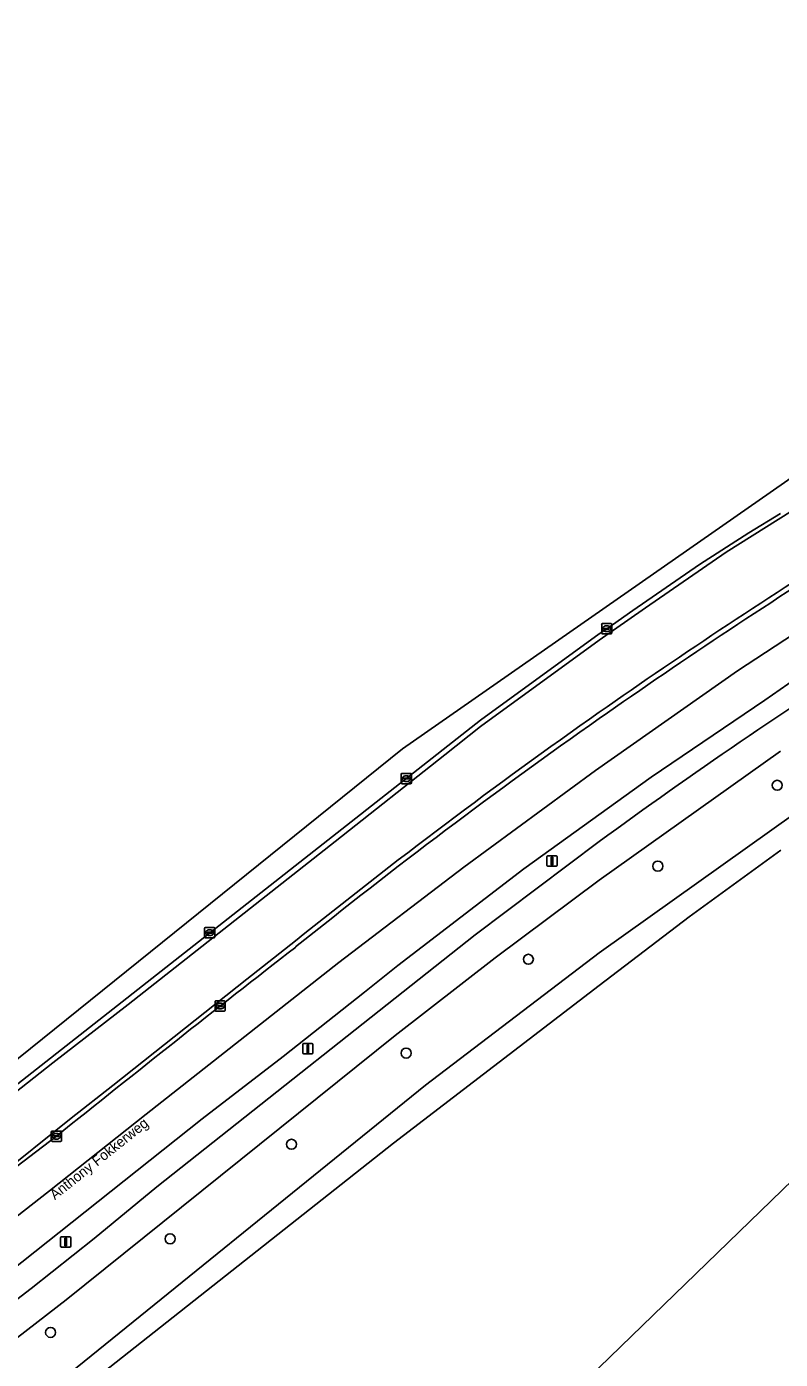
# Model space of a CAD drawing. Extents: x 157132 to 159279, y 384991 to 386650.
# Drawn here: x 157444 to 157517.7, y 386258 to 386388.3 of the extents above; entities that cross this region are included whole.
import ezdxf

# ---------------------------------------------------------------- set-up
doc = ezdxf.new("R2010")
doc.units = 0
for name, color, linetype in [('IMGEO_Berm_groen', 7, 'Continuous'), ('IMGEO_Berm_open', 7, 'Continuous'), ('IMGEO_Boom', 7, 'Continuous'), ('IMGEO_Bouwland', 7, 'Continuous'), ('IMGEO_Fietspad_gesloten', 7, 'Continuous'), ('IMGEO_Gemengd_bos', 7, 'Continuous'), ('IMGEO_Groenvoorziening', 7, 'Continuous'), ('IMGEO_Kolk', 7, 'Continuous'), ('IMGEO_Lichtmast', 7, 'Continuous'), ('IMGEO_Openbare_ruimte_label', 7, 'Continuous'), ('IMGEO_Rijbaan_regionaal_gesloten', 7, 'Continuous'), ('IMGEO_Waterloop', 7, 'Continuous')]:
    doc.layers.add(name, color=color, linetype=linetype)

msp = doc.modelspace()

# ---------------------------------------------------------------- linework, layer by layer
at = {"layer": 'IMGEO_Berm_groen'}
for points in [[(157600.92, 386383.14), (157591.05, 386378.99), (157586.15, 386376.91), (157579.93, 386374.13), (157567.37, 386368.14), (157561.71, 386365.34), (157551.54, 386360.02), (157543.78, 386355.89), (157542.41, 386355.13), (157541.08, 386354.3), (157528.8, 386347.2), (157512.41, 386336.92), (157504.51, 386331.46), (157500, 386328.31), (157488.4, 386319.87), (157484.89, 386317.1), (157474.18, 386308.64), (157453.95, 386292.68), (157446.58, 386286.98), (157440.97, 386282.58), (157431.49, 386275.14), (157425.2, 386270.24), (157416.72, 386263.55), (157406.53, 386255.85)], [(157598.41, 386367.06), (157586.87, 386361.94), (157568.35, 386353.16), (157556.23, 386346.76), (157542.75, 386339.22), (157532.17, 386332.79), (157519.95, 386325.04), (157516.2, 386322.45), (157505.08, 386314.92), (157492.62, 386305.95), (157480.29, 386296.49), (157477.06, 386293.91), (157469.09, 386287.6), (157461.17, 386281.5), (157432.05, 386258.39), (157424.69, 386252.83)], [(157435.01, 386256.97), (157436.41, 386258.75), (157442.19, 386263.2), (157444.45, 386264.94), (157450.61, 386269.8), (157456.75, 386274.86), (157487.88, 386299.49), (157500, 386308.62)], [(157412.24, 386253.73), (157423.17, 386261.68), (157440.43, 386275.24), (157440.88, 386275.59), (157448.35, 386281.57), (157452.43, 386284.78), (157465.54, 386295.18), (157470.31, 386298.92)]]:
    msp.add_lwpolyline(points, dxfattribs=at)
for centre, radius, start, end in [((157825.13, 385857.63), 566.27, 121.9546, 125.041), ((157808.64, 385886.49), 522.93, 122.4759, 126.1718), ((157825.2, 385858.16), 565.88, 125.0775, 128.84)]:
    msp.add_arc(centre, radius, start, end, dxfattribs=at)
at = {"layer": 'IMGEO_Berm_open'}
for points in [[(157406.53, 386255.85), (157416.72, 386263.55), (157425.2, 386270.24), (157431.49, 386275.14), (157440.97, 386282.58), (157446.58, 386286.98), (157453.95, 386292.68), (157474.18, 386308.64), (157484.89, 386317.1), (157488.4, 386319.87), (157500, 386328.31), (157504.51, 386331.46), (157512.41, 386336.92), (157528.8, 386347.2), (157541.08, 386354.3), (157542.41, 386355.13), (157543.78, 386355.89), (157551.54, 386360.02), (157561.71, 386365.34), (157567.37, 386368.14), (157579.93, 386374.13), (157586.15, 386376.91), (157591.05, 386378.99), (157600.92, 386383.14)], [(157517.72, 386340.7), (157514.63, 386338.8), (157509.82, 386335.71), (157503.3, 386331.22), (157500.74, 386329.43), (157500, 386328.94), (157488.4, 386320.5), (157442.68, 386284.57)], [(157470.31, 386298.92), (157465.54, 386295.18), (157452.43, 386284.78), (157448.35, 386281.57), (157440.88, 386275.59), (157440.43, 386275.24), (157423.17, 386261.68), (157412.24, 386253.73), (157409.61, 386251.73), (157408.58, 386250.95), (157398.43, 386243.83), (157391.35, 386239.06), (157386.96, 386236.1), (157383.37, 386233.76), (157383.65, 386233.28), (157385.33, 386234.37), (157389.31, 386237.13), (157407.86, 386250), (157411.47, 386252.75), (157418.46, 386257.79), (157425.84, 386263.47), (157434.7, 386270.29), (157439.77, 386274.36), (157446.92, 386279.81)]]:
    msp.add_lwpolyline(points, dxfattribs=at)
for centre, radius, start, end in [((157825.13, 385857.63), 566.27, 121.9546, 125.041), ((157824.73, 385858.25), 565.03, 121.9528, 125.0788), ((157825.2, 385858.16), 565.88, 125.0775, 128.84), ((157825.2, 385857.55), 565.88, 125.0775, 128.84), ((158559.36, 384896.8), 1774.89, 127.84901, 128.81164)]:
    msp.add_arc(centre, radius, start, end, dxfattribs=at)
at = {"layer": 'IMGEO_Boom'}
for centre in [(157517.41, 386314.12), (157505.73, 386306.22), (157493.07, 386297.11), (157481.12, 386287.94), (157469.91, 386279.02), (157458.04, 386269.78), (157446.35, 386260.63)]:
    msp.add_circle(centre, 0.489, dxfattribs=at)
at = {"layer": 'IMGEO_Bouwland'}
msp.add_lwpolyline([(157517.75, 386307.77), (157508.79, 386301.27), (157500, 386294.54), (157479.88, 386279.13), (157447.02, 386253.2), (157451.27, 386250), (157464.86, 386239.42), (157474.82, 386232.84), (157486.18, 386243.84), (157492.55, 386250), (157496.17, 386253.5), (157500, 386257.21), (157551.55, 386307.16)], dxfattribs=at)
at = {"layer": 'IMGEO_Fietspad_gesloten'}
for points in [[(157400.94, 386220.73), (157435.37, 386252.77), (157436.96, 386252.72), (157439.25, 386254.48), (157439.05, 386257), (157447.87, 386263.8), (157480.03, 386289.67), (157489.83, 386297.27), (157500, 386304.86), (157517.71, 386317.46)], [(157500, 386308.62), (157487.88, 386299.49), (157456.75, 386274.86), (157450.61, 386269.8), (157444.45, 386264.94), (157442.19, 386263.2), (157436.41, 386258.75), (157435.01, 386256.97), (157428.51, 386249.87), (157426.33, 386247.81), (157422.92, 386244.79), (157413.98, 386236.61), (157398.68, 386222.53)]]:
    msp.add_lwpolyline(points, dxfattribs=at)
msp.add_arc((157808.64, 385886.49), 522.93, 122.4759, 126.1718, dxfattribs=at)
at = {"layer": 'IMGEO_Gemengd_bos'}
msp.add_lwpolyline([(157592.6, 386347.15), (157589.03, 386343.68), (157551.55, 386307.16), (157500, 386257.21), (157496.17, 386253.5), (157492.55, 386250), (157486.18, 386243.84), (157474.82, 386232.84)], dxfattribs=at)
at = {"layer": 'IMGEO_Groenvoorziening'}
msp.add_lwpolyline([(157517.71, 386317.46), (157500, 386304.86), (157489.83, 386297.27), (157480.03, 386289.67), (157447.87, 386263.8), (157439.05, 386257), (157439.25, 386254.48), (157440.24, 386253.45), (157442.98, 386251.07), (157444.22, 386250), (157444.46, 386249.78), (157446.02, 386252.41), (157445.55, 386253.01), (157444.84, 386253.9), (157483, 386284.82), (157500, 386297.74), (157524.03, 386314.84)], dxfattribs=at)
at = {"layer": 'IMGEO_Kolk'}
for p, q in [((157500.24, 386329), (157500.24, 386329.86)), ((157500.31, 386329.93), (157501.16, 386329.93)), ((157501.24, 386329.86), (157501.24, 386329)), ((157501.16, 386328.93), (157500.31, 386328.93)), ((157500.49, 386329.42), (157500.49, 386329.44)), ((157500.93, 386329.39), (157500.53, 386329.39)), ((157500.54, 386329.47), (157500.94, 386329.47)), ((157500.72, 386329.71), (157500.75, 386329.71)), ((157500.75, 386329.15), (157500.72, 386329.15)), ((157500.98, 386329.44), (157500.98, 386329.42)), ((157480.64, 386314.36), (157480.64, 386315.21)), ((157480.71, 386315.28), (157481.56, 386315.28)), ((157481.56, 386314.28), (157480.71, 386314.28)), ((157480.89, 386314.78), (157480.89, 386314.79)), ((157481.33, 386314.74), (157480.93, 386314.74)), ((157480.94, 386314.83), (157481.33, 386314.83)), ((157481.12, 386315.06), (157481.15, 386315.06)), ((157481.15, 386314.5), (157481.12, 386314.5)), ((157481.38, 386314.79), (157481.38, 386314.78)), ((157481.64, 386315.21), (157481.64, 386314.36)), ((157461.41, 386299.28), (157461.41, 386300.14)), ((157461.48, 386300.21), (157462.33, 386300.21)), ((157461.9, 386299.99), (157461.92, 386299.99)), ((157462.41, 386300.14), (157462.41, 386299.28)), ((157462.33, 386299.21), (157461.48, 386299.21)), ((157461.67, 386299.7), (157461.67, 386299.72)), ((157461.71, 386299.75), (157462.11, 386299.75)), ((157462.1, 386299.67), (157461.71, 386299.67)), ((157461.92, 386299.43), (157461.89, 386299.43)), ((157462.15, 386299.72), (157462.15, 386299.7)), ((157462.43, 386292.11), (157462.43, 386292.97)), ((157462.5, 386293.04), (157463.36, 386293.04)), ((157463.36, 386292.04), (157462.5, 386292.04)), ((157462.69, 386292.53), (157462.69, 386292.55)), ((157462.73, 386292.58), (157463.13, 386292.58)), ((157463.13, 386292.5), (157462.73, 386292.5)), ((157462.92, 386292.82), (157462.94, 386292.82)), ((157462.94, 386292.26), (157462.92, 386292.26)), ((157463.17, 386292.55), (157463.17, 386292.53)), ((157463.43, 386292.97), (157463.43, 386292.11)), ((157446.5, 386280.31), (157447.35, 386280.31)), ((157446.42, 386279.39), (157446.42, 386280.24)), ((157447.35, 386279.31), (157446.5, 386279.31)), ((157446.68, 386279.81), (157446.68, 386279.82)), ((157446.72, 386279.86), (157447.12, 386279.86)), ((157447.12, 386279.77), (157446.72, 386279.77)), ((157446.91, 386280.09), (157446.94, 386280.09)), ((157446.93, 386279.53), (157446.91, 386279.53)), ((157447.17, 386279.82), (157447.17, 386279.81)), ((157447.42, 386280.24), (157447.42, 386279.39))]:
    msp.add_line(p, q, dxfattribs=at)
for points in [[(157500.24, 386329), (157500.24, 386329.86)], [(157500.31, 386329.93), (157501.16, 386329.93)], [(157501.24, 386329.86), (157501.24, 386329)], [(157501.16, 386328.93), (157500.31, 386328.93)], [(157480.64, 386314.36), (157480.64, 386315.21)], [(157480.71, 386315.28), (157481.56, 386315.28)], [(157481.56, 386314.28), (157480.71, 386314.28)], [(157481.64, 386315.21), (157481.64, 386314.36)], [(157461.41, 386299.28), (157461.41, 386300.14)], [(157461.48, 386300.21), (157462.33, 386300.21)], [(157462.41, 386300.14), (157462.41, 386299.28)], [(157462.33, 386299.21), (157461.48, 386299.21)], [(157462.43, 386292.11), (157462.43, 386292.97)], [(157462.5, 386293.04), (157463.36, 386293.04)], [(157463.36, 386292.04), (157462.5, 386292.04)], [(157463.43, 386292.97), (157463.43, 386292.11)], [(157446.5, 386280.31), (157447.35, 386280.31)], [(157446.42, 386279.39), (157446.42, 386280.24)], [(157447.35, 386279.31), (157446.5, 386279.31)], [(157447.42, 386280.24), (157447.42, 386279.39)]]:
    msp.add_lwpolyline(points, dxfattribs=at)
for centre, radius, start, end in [((157500.31, 386329.85), 0.0765, 91.552, 178.448), ((157500.31, 386329.85), 0.0765, 91.552, 178.448), ((157501.16, 386329.85), 0.0765, 1.552, 88.448), ((157501.16, 386329.85), 0.0765, 1.552, 88.448), ((157500.31, 386329.01), 0.0765, 181.552, 268.448), ((157500.31, 386329.01), 0.0765, 181.552, 268.448), ((157500.54, 386329.43), 0.0403, 85.8775, 175.7526), ((157500.53, 386329.42), 0.0366, 178.938, 274.7102), ((157500.94, 386329.43), 0.043, 264.8664, 352.4533), ((157500.94, 386329.43), 0.0386, 1.7309, 96.639), ((157501.16, 386329.01), 0.0765, 271.552, 358.448), ((157501.16, 386329.01), 0.0765, 271.552, 358.448), ((157480.71, 386315.21), 0.0765, 91.552, 178.448), ((157480.71, 386315.21), 0.0765, 91.552, 178.448), ((157480.71, 386314.36), 0.0765, 181.552, 268.448), ((157480.71, 386314.36), 0.0765, 181.552, 268.448), ((157480.93, 386314.79), 0.0403, 85.8775, 175.7526), ((157480.93, 386314.78), 0.0366, 178.938, 274.7102), ((157481.34, 386314.79), 0.0386, 1.7309, 96.639), ((157481.34, 386314.78), 0.043, 264.8664, 352.4533), ((157481.56, 386315.21), 0.0765, 1.552, 88.448), ((157481.56, 386315.21), 0.0765, 1.552, 88.448), ((157481.56, 386314.36), 0.0765, 271.552, 358.448), ((157481.56, 386314.36), 0.0765, 271.552, 358.448), ((157461.48, 386300.14), 0.0765, 91.552, 178.448), ((157461.48, 386300.14), 0.0765, 91.552, 178.448), ((157462.33, 386300.14), 0.0765, 1.552, 88.448), ((157462.33, 386300.14), 0.0765, 1.552, 88.448), ((157461.48, 386299.29), 0.0765, 181.552, 268.448), ((157461.48, 386299.29), 0.0765, 181.552, 268.448), ((157461.71, 386299.71), 0.0403, 85.8775, 175.7526), ((157461.7, 386299.7), 0.0366, 178.938, 274.7102), ((157462.11, 386299.71), 0.043, 264.8664, 352.4533), ((157462.11, 386299.72), 0.0386, 1.7309, 96.639), ((157462.33, 386299.29), 0.0765, 271.552, 358.448), ((157462.33, 386299.29), 0.0765, 271.552, 358.448), ((157462.51, 386292.96), 0.0765, 91.552, 178.448), ((157462.51, 386292.96), 0.0765, 91.552, 178.448), ((157462.51, 386292.11), 0.0765, 181.552, 268.448), ((157462.51, 386292.11), 0.0765, 181.552, 268.448), ((157462.73, 386292.54), 0.0403, 85.8775, 175.7526), ((157462.73, 386292.53), 0.0366, 178.938, 274.7102), ((157463.13, 386292.54), 0.0386, 1.7309, 96.639), ((157463.13, 386292.54), 0.043, 264.8664, 352.4533), ((157463.35, 386292.96), 0.0765, 1.552, 88.448), ((157463.35, 386292.96), 0.0765, 1.552, 88.448), ((157463.35, 386292.11), 0.0765, 271.552, 358.448), ((157463.35, 386292.11), 0.0765, 271.552, 358.448), ((157446.5, 386280.24), 0.0765, 91.552, 178.448), ((157446.5, 386280.24), 0.0765, 91.552, 178.448), ((157447.35, 386280.24), 0.0765, 1.552, 88.448), ((157447.35, 386280.24), 0.0765, 1.552, 88.448), ((157446.5, 386279.39), 0.0765, 181.552, 268.448), ((157446.5, 386279.39), 0.0765, 181.552, 268.448), ((157446.72, 386279.82), 0.0403, 85.8775, 175.7526), ((157446.72, 386279.81), 0.0366, 178.938, 274.7102), ((157447.13, 386279.82), 0.0386, 1.7309, 96.639), ((157447.12, 386279.81), 0.043, 264.8664, 352.4533), ((157447.35, 386279.39), 0.0765, 271.552, 358.448), ((157447.35, 386279.39), 0.0765, 271.552, 358.448)]:
    msp.add_arc(centre, radius, start, end, dxfattribs=at)
for centre, major_axis, ratio, start_param, end_param in [((157500.72, 386329.43), (-0.387, 0.002), 0.722429, 4.712389, 7.853982), ((157500.75, 386329.43), (-0.39, 0.002), 0.717154, 1.570796, 4.712389), ((157481.12, 386314.78), (-0.387, 0.002), 0.722429, 4.712389, 7.853982), ((157481.15, 386314.78), (-0.39, 0.002), 0.717154, 1.570796, 4.712389), ((157461.89, 386299.71), (-0.387, 0.002), 0.722429, 4.712389, 7.853982), ((157461.92, 386299.71), (-0.39, 0.002), 0.717154, 1.570796, 4.712389), ((157462.92, 386292.54), (-0.387, 0.002), 0.722429, 4.712389, 7.853982), ((157462.94, 386292.54), (-0.39, 0.002), 0.717154, 1.570796, 4.712389), ((157446.91, 386279.81), (-0.387, 0.002), 0.722429, 4.712389, 7.853982), ((157446.93, 386279.81), (-0.39, 0.002), 0.717154, 1.570796, 4.712389)]:
    msp.add_ellipse(centre, major_axis=major_axis, ratio=ratio, start_param=start_param, end_param=end_param, dxfattribs=at)
at = {"layer": 'IMGEO_Lichtmast'}
for p, q in [((157494.89, 386306.32), (157494.89, 386307.12)), ((157494.89, 386307.12), (157494.89, 386306.32)), ((157494.99, 386307.22), (157495.78, 386307.22)), ((157495.78, 386307.22), (157494.99, 386307.22)), ((157495.88, 386307.12), (157495.88, 386306.32)), ((157495.88, 386306.32), (157495.88, 386307.12)), ((157495.78, 386306.22), (157494.99, 386306.22)), ((157494.99, 386306.22), (157495.78, 386306.22)), ((157471.01, 386287.97), (157471.01, 386288.77)), ((157471.01, 386288.77), (157471.01, 386287.97)), ((157471.11, 386288.87), (157471.9, 386288.87)), ((157471.9, 386288.87), (157471.11, 386288.87)), ((157472, 386288.77), (157472, 386287.97)), ((157472, 386287.97), (157472, 386288.77)), ((157471.9, 386287.87), (157471.11, 386287.87)), ((157471.11, 386287.87), (157471.9, 386287.87)), ((157447.33, 386269.08), (157447.33, 386269.88)), ((157447.33, 386269.88), (157447.33, 386269.08)), ((157447.43, 386269.98), (157448.22, 386269.98)), ((157448.22, 386269.98), (157447.43, 386269.98)), ((157448.32, 386269.88), (157448.32, 386269.08)), ((157448.32, 386269.08), (157448.32, 386269.88)), ((157448.22, 386268.98), (157447.43, 386268.98)), ((157447.43, 386268.98), (157448.22, 386268.98))]:
    msp.add_line(p, q, dxfattribs=at)
for points in [[(157495.31, 386307.09), (157495.46, 386307.09), (157495.46, 386306.34), (157495.31, 386306.34), (157495.31, 386307.09)], [(157471.43, 386288.74), (157471.58, 386288.74), (157471.58, 386287.99), (157471.43, 386287.99), (157471.43, 386288.74)], [(157447.75, 386269.86), (157447.9, 386269.86), (157447.9, 386269.11), (157447.75, 386269.11), (157447.75, 386269.86)]]:
    msp.add_lwpolyline(points, dxfattribs=at)
for centre, start, end in [((157494.99, 386307.12), 90, 180), ((157494.99, 386307.12), 90, 180), ((157495.78, 386307.12), 0, 90), ((157495.78, 386307.12), 360, 90), ((157494.99, 386306.32), 180, 270), ((157494.99, 386306.32), 180, 270), ((157495.78, 386306.32), 270, 0), ((157495.78, 386306.32), 270, 0), ((157471.11, 386288.77), 90, 180), ((157471.11, 386288.77), 90, 180), ((157471.9, 386288.77), 0, 90), ((157471.9, 386288.77), 360, 90), ((157471.11, 386287.97), 180, 270), ((157471.11, 386287.97), 180, 270), ((157471.9, 386287.97), 270, 0), ((157471.9, 386287.97), 270, 0), ((157447.43, 386269.88), 90, 180), ((157447.43, 386269.88), 90, 180), ((157448.22, 386269.88), 0, 90), ((157448.22, 386269.88), 360, 90), ((157447.43, 386269.08), 180, 270), ((157447.43, 386269.08), 180, 270), ((157448.22, 386269.08), 270, 0), ((157448.22, 386269.08), 270, 0)]:
    msp.add_arc(centre, 0.1, start, end, dxfattribs=at)
at = {"layer": 'IMGEO_Rijbaan_regionaal_gesloten'}
for points in [[(157605.48, 386388.3), (157523.83, 386347.69), (157480.76, 386317.69), (157404.31, 386256.14), (157367.32, 386233.16)], [(157601.75, 386372.59), (157587.17, 386366.22), (157572.76, 386359.43), (157562.16, 386354.16), (157548.16, 386346.64), (157537.84, 386340.64), (157523.61, 386331.94), (157513.51, 386325.31), (157499.63, 386315.57), (157486.75, 386306.11), (157474.53, 386296.81), (157455.69, 386281.96), (157446.25, 386274.48), (157430.5, 386262.2), (157420.26, 386254.38), (157411.04, 386247.62), (157399.37, 386239.35), (157382.38, 386227.42), (157373.63, 386221.32), (157375.45, 386217.91), (157379.15, 386220.37), (157386.81, 386225.47), (157387.95, 386226.15)], [(157420.26, 386254.38), (157430.5, 386262.2), (157446.25, 386274.48), (157455.69, 386281.96), (157474.53, 386296.81), (157486.75, 386306.11), (157499.63, 386315.57), (157513.51, 386325.31), (157523.61, 386331.94), (157537.84, 386340.64), (157548.16, 386346.64), (157562.16, 386354.16), (157572.76, 386359.43), (157587.17, 386366.22), (157601.75, 386372.59)], [(157492.62, 386305.95), (157505.08, 386314.92), (157516.2, 386322.45), (157519.95, 386325.04), (157532.17, 386332.79), (157542.75, 386339.22), (157556.23, 386346.76), (157568.35, 386353.16), (157586.87, 386361.94), (157598.41, 386367.06)], [(157442.68, 386284.57), (157488.4, 386320.5), (157500, 386328.94), (157500.74, 386329.43), (157503.3, 386331.22), (157509.82, 386335.71), (157514.63, 386338.8), (157517.72, 386340.7)], [(157424.69, 386252.83), (157432.05, 386258.39), (157461.17, 386281.5), (157469.09, 386287.6), (157477.06, 386293.91), (157480.29, 386296.49), (157492.62, 386305.95)], [(157446.92, 386279.81), (157439.77, 386274.36), (157434.7, 386270.29), (157425.84, 386263.47), (157418.46, 386257.79)]]:
    msp.add_lwpolyline(points, dxfattribs=at)
for centre, radius, start, end in [((157824.73, 385858.25), 565.03, 121.9528, 125.0788), ((157825.2, 385857.55), 565.88, 125.0775, 128.84), ((158559.36, 384896.8), 1774.89, 127.84901, 128.81164)]:
    msp.add_arc(centre, radius, start, end, dxfattribs=at)
at = {"layer": 'IMGEO_Waterloop'}
msp.add_lwpolyline([(157524.03, 386314.84), (157500, 386297.74), (157483, 386284.82), (157444.84, 386253.9), (157445.55, 386253.01), (157446.02, 386252.41), (157447.02, 386253.2), (157479.88, 386279.13), (157500, 386294.54), (157508.79, 386301.27), (157517.75, 386307.77)], dxfattribs=at)

# ---------------------------------------------------------------- texts
at = {"layer": 'IMGEO_Openbare_ruimte_label'}
msp.add_text('Anthony Fokkerweg', height=1, rotation=38.5435, dxfattribs=at).set_placement((157446.77, 386273.54))

doc.saveas('drawing.dxf')
